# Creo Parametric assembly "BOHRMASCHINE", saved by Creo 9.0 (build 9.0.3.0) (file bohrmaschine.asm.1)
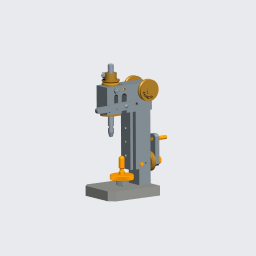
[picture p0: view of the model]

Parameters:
  ERSTELLER = "ARINDA"
  BENENNUNG = "XXX"
  TEILETYP = "K"

Other parameters: MASSE, TRANSLATION1_STATIC_FRICTION, TRANSLATION1_KINETIC_FRICTION, TRANSLATION1_RESTITUTION, TRANSLATION1_MINIMUM_LIMIT, TRANSLATION1_MAXIMUM_LIMIT, TRANSLATION1_ZERO_POSITION, ROTATION1_STATIC_FRICTION, ROTATION1_KINETIC_FRICTION, ROTATION1_CONTACT_RADIUS, ROTATION1_RESTITUTION, ROTATION1_MINIMUM_LIMIT, ROTATION1_MAXIMUM_LIMIT, ROTATION1_ZERO_POSITION

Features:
  1. coordinate system
  2. datum plane "A_RECHTS_Y-Z"
  3. datum plane "A_OBEN_X-Z"
  4. datum plane "A_VORNE_X-Y"
  5. datum axis
  6. datum axis
  7. datum axis
  8. datum point "APNT0"
  9. component "BODENPLATTE"
  10. component "STÄNDER"
  11. component "DIN_912"
  12. component "BOHRMASCHINENKOPF"
  13. component "ISO7434_M4X4"
  14. component "FÜHRUNGSLEISTE"
  15. component "DIN913_45H"
  16. component "ISO4032_1"
  17. pattern
  18. component "ISO2338"
  19. component "ISO2338"
  20. component "DIN_912"
  21. component "RÄNDELSCHRAUBE"
  22. component "ANTRIEBSSCHEIBE"
  23. component "ISO7435"
  24. component "ISO4032_1"
  25. component "ISO7090T1"
  26. component "KURBEL"
  27. component "ISO4032_1"
  28. component "ISO2338"
  29. component
  30. component
  31. component
  32. component
  33. component
  34. component "HEBEL"

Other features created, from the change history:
  planar section "XSEC0001" (2 times)
  planar section "XSEC0002"
  feature "Motor 1"
  component "DIN7513M3BX6.PRT"
  component "RIEMEN.PRT"
  group "COPIED_GROUP"

Other named items: AA_X, AA_Y, AA_Z, ACS0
